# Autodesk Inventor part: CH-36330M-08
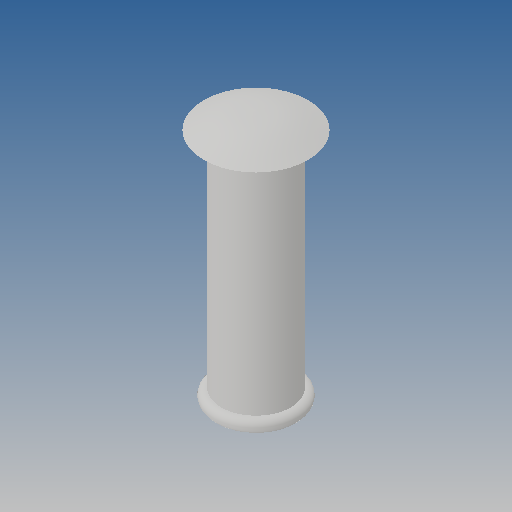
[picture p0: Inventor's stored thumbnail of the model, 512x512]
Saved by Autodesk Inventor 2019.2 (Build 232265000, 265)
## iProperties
Created: 2012-09
Part Number: CH-36330M-08
Material: Ogólny
Document SubType Name: Modeling
Designer: CADENGINEERING4
Density: 1 g/cm^3
Appearance: Domyślna
Author: CADENGINEERING4
Revision Number: ÈÎºÎ
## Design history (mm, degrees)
feature "Ô²½Ç2"
node "Bryła1"
